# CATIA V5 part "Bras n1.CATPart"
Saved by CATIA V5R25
Part number: Part9
Bounding box of the stored display mesh (mm): x -10 to 148.432, y -12.5 to 12.5, z -0.285 to 12.862
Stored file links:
  C:\Users\m000605\Desktop\Projet FAB liseuse\Bras n1.CATPart
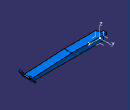
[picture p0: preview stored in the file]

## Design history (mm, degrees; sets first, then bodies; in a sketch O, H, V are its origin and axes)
AxisSystem1: origin (0, 0, 0), X (1, 0, 0), Y (0, 1, 0), Z (0, 0, 1)
Set1
  Sketch1 on XY plane of AxisSystem1, origin (0, 0, 0), H (1, 0, 0), V (0, 1, 0)
    line L1 (-145, 7.5) -> (145, 7.5)
    line L2 (145, 7.5) -> (145, -7.5)
    line L3 (145, -7.5) -> (-145, -7.5)
    line L4 (-145, -7.5) -> (-145, 7.5)
    length L1 = 290
    length L2 = 15
    horizontal: L1 H, L3 H
    vertical: L2 V, L4 V
    symmetry: L3 L1 H, L2 L4 V
Body1 (main body)
  Pad1: profile Sketch1, direction (0, 0, 1), length 10
  Sketch2 on face of Pad1 from Sketch1.L1, origin (0, 7.5, 0), H (-1, 0, 0), V (0, 0, 1)
    circle A1 centre (137.45, 5) radius 2.55
    point P1 (137.45, 5)
    reference projected line E1 (145, 0) -> (145, 10) from edge [face of Pad1 from Sketch1.L4 | face of Pad1 from Sketch1.L1]
    reference projected line E2 (-145, 0) -> (145, 0) from edge [start face of Pad1 | face of Pad1 from Sketch1.L1]
    radius A1 = 2.55
    distance A1 E1 = 5
    distance P1 E2 = 5
  Pocket1: profile Sketch2, direction (0, -1, 0), through (limit type 6)
  Sketch3 on ZX plane of AxisSystem1, origin (0, 0, 0), H (0, 0, 1), V (1, 0, 0)
    point P1 (0, 145)
    line L1 (0, 145) -> (10, 145)
    point P2 (10, 145)
    reference projected point E1 (10, 145) from vertex [face of Pad1 from Sketch1.L1 | end face of Pad1 | face of Pad1 from Sketch1.L2]
    line L2 (10, 145) -> (0, 139)
    point P3 (0, 139)
    line L3 (0, 139) -> (0, 145)
    length L1 = 10
    length L3 = 6
    coincidence: P1 V, P2 E1, P3 V
    vertical: L3 V
  Pocket2: profile Sketch3, direction (0, -1, 0), through (limit type 6), offset 6, opposite side length 8
  Sketch4 on face of Pocket2 from Sketch3.L2, origin (102.2059, 0, -61.3235), H (0, 1, 0), V (0.5145, 0, 0.8575)
    line L1 (12.5, 86.5149) -> (12.5, 71.5149)
    line L2 (12.5, 71.5149) -> (-12.5, 71.5149)
    line L3 (-12.5, 71.5149) -> (-12.5, 86.5149)
    reference projected line E1 (-7.5, 71.5149) -> (7.5, 71.5149) from edge [start face of Pad1 | face of Pocket2 from Sketch3.L2]
    line L4 (-12.5, 86.5149) -> (-7.5, 86.5149)
    point P5 (-7.5, 86.5149)
    line L5 (12.5, 86.5149) -> (7.5, 86.5149)
    line L6 (7.5, 86.5149) -> (7.5, 83.1768)
    line L7 (7.5, 83.1768) -> (-7.5, 83.1768)
    line L8 (-7.5, 83.1768) -> (-7.5, 86.5149)
    point P9 (-7.5, 86.5149)
    reference projected line E2 (7.5, 83.1768) -> (7.5, 71.5149) from edge [face of Pocket2 from Sketch3.L2 | face of Pad1 from Sketch1.L1]
    reference projected line E3 (-7.5, 83.1768) -> (-7.5, 71.5149) from edge [face of Pad1 from Sketch1.L3 | face of Pocket2 from Sketch3.L2]
    reference projected line E4 (-7.5, 83.1768) -> (7.5, 83.1768) from edge [face of Pocket2 from Sketch3.L2 | end face of Pad1]
    length L5 = 5
    length L3 = 15
    horizontal: L2 H, L4 H, L5 H, L7 H
    vertical: L1 V, L3 V, L6 V
    symmetry: L1 L3 V
    coincidence: L2 E1, L8 P5, E2 L6, E3 L8, L7 E4, P9 P5, L5 L4
  Pad2: profile Sketch4, direction (0.8575, 0, -0.5145), length 2
  Sketch5 on end face of Pad2, origin (103.9209, 0, -62.3525), H (0, 1, 0), V (0.5145, 0, 0.8575)
    line L1 (-7.5, 83.1768) -> (7.5, 83.1768)
    line L2 (7.5, 83.1768) -> (7.5, 78.1768)
    line L3 (7.5, 78.1768) -> (-7.5, 78.1768)
    line L4 (-7.5, 78.1768) -> (-7.5, 83.1768)
    reference projected line E1 (7.5, 86.5149) -> (7.5, 83.1768) from edge [face of Pad2 from Sketch4.L6 | end face of Pad2]
    reference projected line E2 (-7.5, 83.1768) -> (-7.5, 86.5149) from edge [face of Pad2 from Sketch4.L8 | end face of Pad2]
    reference projected line E3 (7.5, 83.1768) -> (-7.5, 83.1768) from edge [face of Pad2 from Sketch4.L7 | end face of Pad2]
    length L2 = 5
    horizontal: L1 H, L3 H
    vertical: L2 V, L4 V
    coincidence: L2 E1, L4 E2, E3 L1
  Pocket3: profile Sketch5, direction (-0.8575, 0, 0.5145), through (limit type 6)
  Fillet1: radius 2, on edge [face of Pad2 from Sketch4.L2 | end face of Pad2]
  Chamfer1: length 72, angle 3, on edge [end face of Pad1 | face of Pocket3 from Sketch5.L3]
  Split1: SplitPlane YZ plane of AxisSystem1
  Sketch6 on face of Split1, origin (0, 0, 0), H (0, -1, 0), V (0, 0, 1)
    line L1 (-3, 7) -> (3, 7)
    line L2 (3, 7) -> (3, 3)
    line L3 (3, 3) -> (-3, 3)
    line L4 (-3, 3) -> (-3, 7)
    reference projected line E1 (-7.5, 0) -> (7.5, 0) from edge [start face of Pad1 | face of Split1]
    length L1 = 6
    length L2 = 4
    distance L3 E1 = 3
    horizontal: L1 H, L3 H
    vertical: L2 V, L4 V
    symmetry: L4 L2 V
  Pad3: profile Sketch6, direction (-1, 0, 0), length 10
